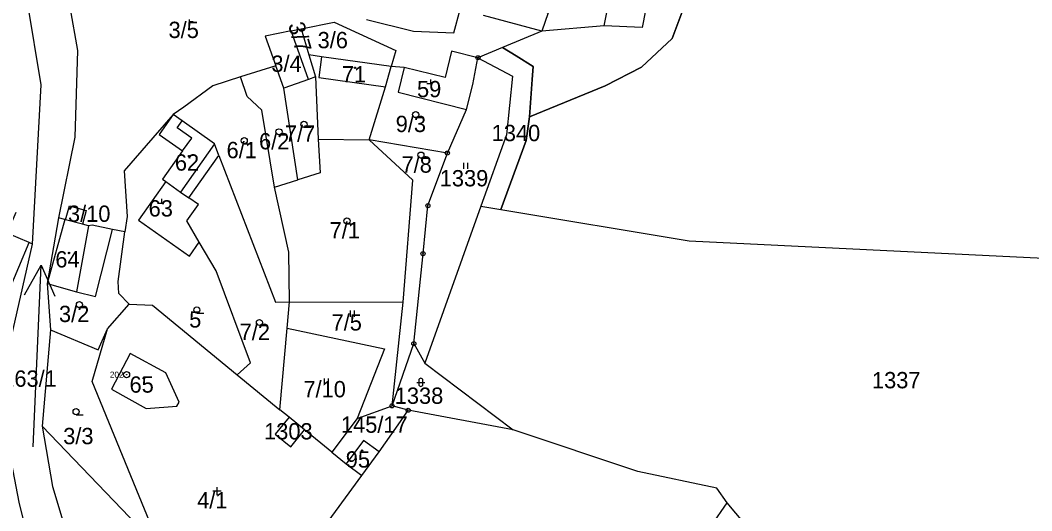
# Model space of a CAD drawing. Extents: x -564516 to -563466, y -1163913 to -1163170.
# Drawn here: x -564146.8 to -563898.7, y -1163610.3 to -1163490 of the extents above; entities that cross this region are included whole.
import ezdxf

# ---------------------------------------------------------------- set-up
doc = ezdxf.new("R2010")
doc.units = 0
for name, color, linetype in [('_ZOV', 7, 'Continuous'), ('Hranice parcel', 7, 'Continuous'), ('Parcelní čísla', 7, 'Continuous'), ('Vnitřní kresba', 7, 'Continuous'), ('Značky bodu BP', 7, 'Continuous'), ('Značky budov', 7, 'Continuous'), ('Značky kultur', 7, 'Continuous')]:
    doc.layers.add(name, color=color, linetype=linetype)

msp = doc.modelspace()

# ---------------------------------------------------------------- linework, layer by layer
at = {"layer": '_ZOV'}
msp.add_line((-564143.63, -1163594.64), (-564141.71, -1163550.07), dxfattribs=at)
msp.add_lwpolyline([(-564145.74, -1163557.34), (-564141.71, -1163550.07), (-564138.31, -1163557.66)], dxfattribs=at)
at = {"layer": 'Hranice parcel'}
for p, q in [((-564003.59, -1163491.36), (-564001.49, -1163481.27)), ((-564018.83, -1163492.67), (-564033.19, -1163488.88)), ((-564080.36, -1163492.63), (-564077.86, -1163492.12)), ((-564076.1, -1163504.52), (-564080.36, -1163492.63)), ((-564077.86, -1163492.12), (-564075.98, -1163498.54)), ((-564018.83, -1163492.67), (-564028.46, -1163496.69)), ((-564003.59, -1163491.36), (-564018.83, -1163492.67)), ((-564028.46, -1163496.69), (-564034.52, -1163499.22)), ((-564075.98, -1163498.54), (-564074.41, -1163503.9)), ((-564084.1, -1163501.17), (-564092.76, -1163503.91)), ((-564082.12, -1163506.7), (-564084.1, -1163501.17)), ((-564052.59, -1163501.62), (-564055.78, -1163501.39)), ((-564021.23, -1163504.52), (-564020.95, -1163501.38)), ((-564076.1, -1163504.52), (-564082.12, -1163506.7)), ((-564074.41, -1163503.9), (-564076.1, -1163504.52)), ((-564074.41, -1163503.9), (-564073.71, -1163519.16)), ((-564021.9, -1163513.74), (-564021.23, -1163504.52)), ((-564078.72, -1163529.15), (-564082.12, -1163506.7)), ((-564021.9, -1163513.74), (-564003.29, -1163506.07)), ((-564042.03, -1163522.61), (-564037.34, -1163511.95)), ((-564109.29, -1163513.17), (-564114.3, -1163518.86)), ((-564022.73, -1163519.5), (-564021.9, -1163513.74)), ((-564073.71, -1163519.16), (-564061.18, -1163519.39)), ((-564042.03, -1163522.61), (-564061.18, -1163519.39)), ((-564028.91, -1163536.42), (-564022.73, -1163519.5)), ((-564105.44, -1163533.59), (-564098.08, -1163523.21)), ((-564084.46, -1163530.94), (-564078.72, -1163529.15)), ((-564135.68, -1163538.95), (-564134.76, -1163535.58)), ((-564134.76, -1163535.58), (-564130.65, -1163536.7)), ((-564130.65, -1163536.7), (-564131.56, -1163540.01)), ((-564033.84, -1163535.6), (-564047.59, -1163574.1)), ((-564033.84, -1163535.6), (-564028.91, -1163536.42)), ((-564137.43, -1163538.5), (-564140.18, -1163554.63)), ((-564131.56, -1163540.01), (-564135.68, -1163538.95)), ((-564130.03, -1163540.41), (-564131.56, -1163540.01)), ((-564129.13, -1163540.27), (-564130.03, -1163540.41)), ((-564124.15, -1163541.32), (-564129.13, -1163540.27)), ((-564121.18, -1163541.94), (-564124.15, -1163541.32)), ((-564149.67, -1163556.63), (-564144.59, -1163544.5)), ((-564143.77, -1163544.97), (-564144.59, -1163544.5)), ((-564140.18, -1163554.63), (-564139.41, -1163565.96)), ((-564120.1, -1163559.69), (-564122.64, -1163557.02)), ((-564125.43, -1163565.71), (-564120.1, -1163559.69)), ((-564081.35, -1163565.54), (-564080.79, -1163559.09)), ((-564080.79, -1163559.09), (-564052.86, -1163559.2)), ((-564055.59, -1163584.6), (-564052.86, -1163559.2)), ((-564139.41, -1163565.96), (-564141.45, -1163589.58)), ((-564083.1, -1163585.56), (-564081.35, -1163565.54)), ((-564055.59, -1163584.6), (-564050.25, -1163569.33)), ((-564050.25, -1163569.33), (-564047.59, -1163574.1)), ((-564047.59, -1163574.1), (-564025.86, -1163590.51)), ((-564093.56, -1163576.99), (-564083.1, -1163585.56)), ((-564064.14, -1163587.67), (-564055.59, -1163584.6)), ((-564051.64, -1163585.68), (-564055.59, -1163584.6)), ((-564080.86, -1163587.4), (-564083.1, -1163585.56)), ((-564025.86, -1163590.51), (-564051.64, -1163585.68)), ((-564141.45, -1163589.58), (-564112.22, -1163619.96)), ((-564077.06, -1163590.51), (-564080.86, -1163587.4)), ((-564064.14, -1163587.67), (-564070.36, -1163596)), ((-564070.36, -1163596), (-564077.06, -1163590.51)), ((-564070.36, -1163596), (-564066.89, -1163598.84)), ((-564063.05, -1163601.67), (-564058.79, -1163595.9)), ((-564066.89, -1163598.84), (-564063.05, -1163601.67)), ((-564092.3, -1163641.63), (-564063.05, -1163601.67)), ((-563945.88, -1163641.11), (-563973.39, -1163608.38))]:
    msp.add_line(p, q, dxfattribs=at)
for points in [[(-564143.77, -1163544.97), (-564141.64, -1163505.89), (-564145.04, -1163485.62), (-564150.7, -1163460.95), (-564167.69, -1163413.52), (-564175.8, -1163398.73), (-564196.49, -1163371.97), (-564199.67, -1163364.72)], [(-563978.16, -1163460.35), (-563977.81, -1163470.18), (-563986.9, -1163494.46), (-563994.41, -1163501.54), (-564003.29, -1163506.07), (-564021.9, -1163513.74)], [(-563986.9, -1163494.46), (-563977.81, -1163470.18), (-563978.16, -1163460.35)], [(-563988.32, -1163461.72), (-563994.27, -1163491.83), (-564003.59, -1163491.36)], [(-564032.65, -1163483.65), (-564032.18, -1163483.66), (-564032.1, -1163484.76), (-564017.32, -1163488.18), (-564018.83, -1163492.67)], [(-564134.63, -1163486.82), (-564132.78, -1163497.42), (-564133.38, -1163518.72), (-564137.43, -1163538.5)], [(-564061.85, -1163489.87), (-564050.33, -1163492.71), (-564040.4, -1163493.1), (-564038.9, -1163487.37)], [(-564080.36, -1163492.63), (-564086.69, -1163493.92), (-564084.1, -1163501.17)], [(-564077.86, -1163492.12), (-564069.81, -1163490.48), (-564054.63, -1163497.47), (-564055.78, -1163501.39)], [(-564028.91, -1163536.42), (-563982.72, -1163544.1), (-563870.61, -1163549.59), (-563828.67, -1163493.21)], [(-564003.29, -1163506.07), (-563994.41, -1163501.54), (-563986.9, -1163494.46)], [(-564034.52, -1163499.22), (-564040.98, -1163497.58), (-564042.58, -1163504.09), (-564052.59, -1163501.62)], [(-564028.46, -1163496.69), (-564025.15, -1163498.74), (-564020.95, -1163501.38), (-564021.23, -1163504.52), (-564021.9, -1163513.74)], [(-564020.95, -1163501.38), (-564025.15, -1163498.74), (-564028.46, -1163496.69)], [(-564055.78, -1163501.39), (-564072.88, -1163498.98), (-564075.98, -1163498.54)], [(-564037.34, -1163511.95), (-564035.8, -1163505.76), (-564034.52, -1163499.22)], [(-564034.52, -1163499.22), (-564026.04, -1163503.72), (-564027.54, -1163518.14), (-564033.84, -1163535.6)], [(-564061.18, -1163519.39), (-564057.24, -1163506.38), (-564055.78, -1163501.39)], [(-564052.59, -1163501.62), (-564054.07, -1163507.64), (-564037.34, -1163511.95)], [(-564092.76, -1163503.91), (-564099.6, -1163506.08), (-564106.7, -1163511.31), (-564109.29, -1163513.17)], [(-564084.46, -1163530.94), (-564087.57, -1163512.11), (-564091.17, -1163508.73), (-564092.76, -1163503.91)], [(-564109.29, -1163513.17), (-564112.74, -1163518.03), (-564107.04, -1163522.06), (-564111.89, -1163529.04), (-564111.07, -1163529.61)], [(-564098.08, -1163523.21), (-564099.13, -1163520.36), (-564107.09, -1163514.73), (-564109.29, -1163513.17)], [(-564021.9, -1163513.74), (-564022.73, -1163519.5), (-564028.91, -1163536.42)], [(-564114.3, -1163518.86), (-564121.28, -1163526.92), (-564120.58, -1163538.19), (-564121.18, -1163541.94)], [(-564073.71, -1163519.16), (-564073.26, -1163527.42), (-564078.72, -1163529.15)], [(-564052.86, -1163559.2), (-564050.52, -1163529.28), (-564061.18, -1163519.39)], [(-564050.25, -1163569.33), (-564048, -1163547.27), (-564046.8, -1163535.5), (-564042.03, -1163522.61)], [(-564098.08, -1163523.21), (-564084.18, -1163559.19), (-564080.79, -1163559.09)], [(-564111.07, -1163529.61), (-564117.77, -1163539.08), (-564105.32, -1163547.88), (-564102.89, -1163544.44)], [(-564111.07, -1163529.61), (-564107.48, -1163532.15), (-564105.44, -1163533.59)], [(-564080.79, -1163559.09), (-564080.89, -1163546.94), (-564084.46, -1163530.94)], [(-564102.89, -1163544.44), (-564105.94, -1163539.23), (-564103.12, -1163535.23), (-564105.44, -1163533.59)], [(-564144.59, -1163544.5), (-564150.02, -1163542.22), (-564147.82, -1163537.06)], [(-564135.68, -1163538.95), (-564135.89, -1163538.9), (-564137.43, -1163538.5)], [(-564140.18, -1163554.63), (-564133.01, -1163556.6), (-564128.31, -1163557.75), (-564124.15, -1163541.32)], [(-564122.64, -1163557.02), (-564122.78, -1163554.08), (-564121.18, -1163541.94)], [(-564141.75, -1163629.73), (-564147.11, -1163608.19), (-564150.44, -1163590.7), (-564149.91, -1163571.99), (-564143.77, -1163544.97)], [(-564093.56, -1163576.99), (-564090.33, -1163574.05), (-564098.76, -1163551.48), (-564102.89, -1163544.44)], [(-564120.1, -1163559.69), (-564114.4, -1163559.92), (-564093.56, -1163576.99)], [(-564139.41, -1163565.96), (-564127.69, -1163570.84), (-564125.43, -1163565.71)], [(-564112.22, -1163619.96), (-564129.19, -1163578.66), (-564125.43, -1163565.71)], [(-564081.35, -1163565.54), (-564057.47, -1163570.58), (-564064.14, -1163587.67)], [(-564107.84, -1163583.68), (-564111.09, -1163576.51), (-564119.82, -1163571.78), (-564124.45, -1163580.53), (-564115.93, -1163585.25), (-564108.37, -1163584.67), (-564107.84, -1163583.68)], [(-564058.79, -1163595.9), (-564053.56, -1163588.43), (-564051.64, -1163585.68)], [(-564141.45, -1163589.58), (-564138.93, -1163604.36), (-564128.21, -1163640.02)], [(-564080.86, -1163587.4), (-564084.24, -1163591.54), (-564080.45, -1163594.65), (-564077.06, -1163590.51)], [(-563973.39, -1163608.38), (-563975.93, -1163604.8), (-563995.32, -1163600.73), (-564025.86, -1163590.51)], [(-564058.79, -1163595.9), (-564062.63, -1163593.07), (-564066.89, -1163598.84)], [(-564038.32, -1163697.37), (-564037.15, -1163696.07), (-563993.61, -1163632.54), (-563977.25, -1163613.92), (-563973.39, -1163608.38)]]:
    msp.add_lwpolyline(points, dxfattribs=at)
at = {"layer": 'Vnitřní kresba'}
for p, q in [((-564072.88, -1163498.98), (-564073.58, -1163504.08)), ((-564073.58, -1163504.08), (-564057.24, -1163506.38)), ((-564108.3, -1163516.44), (-564107.09, -1163514.73)), ((-564104.75, -1163518.95), (-564108.3, -1163516.44)), ((-564107.04, -1163522.06), (-564104.75, -1163518.95)), ((-564099.13, -1163520.36), (-564107.48, -1163532.15)), ((-564135.89, -1163538.9), (-564140.18, -1163554.63)), ((-564130.03, -1163540.41), (-564133.01, -1163556.6))]:
    msp.add_line(p, q, dxfattribs=at)
at = {"layer": 'Značky bodu BP'}
for centre, radius in [((-564034.52, -1163499.22), 0.5), ((-564034.52, -1163499.22), 0.0303), ((-564042.03, -1163522.61), 0.5), ((-564042.03, -1163522.61), 0.0303), ((-564046.8, -1163535.5), 0.5), ((-564046.8, -1163535.5), 0.0303), ((-564048, -1163547.27), 0.5), ((-564048, -1163547.27), 0.0303), ((-564050.25, -1163569.33), 0.5), ((-564050.25, -1163569.33), 0.0303), ((-564120.72, -1163576.96), 0.75), ((-564120.72, -1163576.96), 0.03), ((-564055.59, -1163584.6), 0.5), ((-564055.59, -1163584.6), 0.0303), ((-564051.64, -1163585.68), 0.5), ((-564051.64, -1163585.68), 0.0303)]:
    msp.add_circle(centre, radius, dxfattribs=at)
at = {"layer": 'Značky budov'}
for centre in [(-564064.7, -1163501.67), (-564105.39, -1163523.36), (-564134.82, -1163547.11), (-564116.56, -1163577.82), (-564062.93, -1163595.56)]:
    msp.add_circle(centre, 0.175, dxfattribs=at)
at = {"layer": 'Značky kultur'}
for p, q in [((-564105.41, -1163489.84), (-564105.41, -1163490.34)), ((-564105.41, -1163490.34), (-564104.41, -1163490.34)), ((-564046.05, -1163505.57), (-564046.05, -1163504.57)), ((-564047.05, -1163505.57), (-564046.05, -1163505.57)), ((-564049.79, -1163513.9), (-564048.04, -1163513.9)), ((-564077.2, -1163516.28), (-564075.45, -1163516.28)), ((-564083.34, -1163518.14), (-564081.59, -1163518.14)), ((-564091.87, -1163520.31), (-564090.12, -1163520.31)), ((-564048.51, -1163523.86), (-564046.76, -1163523.86)), ((-564038.01, -1163526.5), (-564038.01, -1163525)), ((-564037.01, -1163526.5), (-564037.01, -1163525)), ((-564113.1, -1163534.86), (-564112.1, -1163534.86)), ((-564112.1, -1163534.86), (-564112.1, -1163533.86)), ((-564066.65, -1163539.99), (-564064.9, -1163539.99)), ((-564132.3, -1163560.5), (-564130.55, -1163560.5)), ((-564103.49, -1163561.85), (-564101.74, -1163561.85)), ((-564065.8, -1163562.75), (-564065.8, -1163561.25)), ((-564064.8, -1163562.75), (-564064.8, -1163561.25)), ((-564088.14, -1163564.91), (-564086.39, -1163564.91)), ((-564072.15, -1163579.42), (-564072.15, -1163577.92)), ((-564071.15, -1163579.42), (-564071.15, -1163577.92)), ((-564049.54, -1163578.84), (-564047.54, -1163578.84)), ((-564049.04, -1163578.34), (-564049.04, -1163579.34)), ((-564048.04, -1163579.34), (-564048.04, -1163578.34)), ((-564133.11, -1163586.77), (-564131.36, -1163586.77)), ((-564098.53, -1163606.52), (-564098.53, -1163604.52)), ((-564097.53, -1163605.52), (-564099.53, -1163605.52))]:
    msp.add_line(p, q, dxfattribs=at)
for centre in [(-564049.79, -1163513.15), (-564077.2, -1163515.53), (-564083.34, -1163517.39), (-564091.87, -1163519.56), (-564048.51, -1163523.11), (-564066.65, -1163539.24), (-564132.3, -1163559.75), (-564103.49, -1163561.1), (-564088.14, -1163564.16), (-564133.11, -1163586.02)]:
    msp.add_circle(centre, 0.75, dxfattribs=at)
for centre, start, end in [((-564048.54, -1163578.34), 0, 180), ((-564048.54, -1163579.34), 180, 359.9879)]:
    msp.add_arc(centre, 0.5, start, end, dxfattribs=at)

# ---------------------------------------------------------------- texts
at = {"layer": 'Parcelní čísla'}
for s, p in [('3/5', (-564110.43, -1163494.38)), ('3/6', (-564073.86, -1163496.89)), ('3/4', (-564085.2, -1163502.68)), ('71', (-564067.91, -1163505.28)), ('59', (-564049.47, -1163508.91)), ('9/3', (-564054.7, -1163517.45)), ('6/2', (-564088.23, -1163521.69)), ('7/7', (-564081.88, -1163519.83)), ('1340', (-564031.15, -1163519.68)), ('6/1', (-564096.19, -1163523.86)), ('62', (-564108.87, -1163526.91)), ('7/8', (-564053.27, -1163527.41)), ('1339', (-564043.89, -1163530.77)), ('63', (-564115.31, -1163538.16)), ('3/10', (-564135.1, -1163539.47)), ('7/1', (-564070.91, -1163543.54)), ('64', (-564138.2, -1163550.66)), ('3/2', (-564137.31, -1163564.05)), ('5', (-564105.37, -1163565.4)), ('7/5', (-564070.43, -1163566.13)), ('7/2', (-564092.98, -1163568.46)), ('1163/1', (-564154.2, -1163579.92)), ('1337', (-563937.85, -1163580.3)), ('65', (-564120, -1163581.37)), ('7/10', (-564077.34, -1163582.51)), ('1338', (-564054.93, -1163584.11)), ('145/17', (-564068.13, -1163591.21)), ('1303', (-564086.99, -1163592.84)), ('3/3', (-564136.27, -1163594.01)), ('95', (-564066.95, -1163599.75)), ('4/1', (-564103.41, -1163609.77))]:
    msp.add_text(s, height=4, dxfattribs=at).set_placement(p)
msp.add_text('3/7', height=4, rotation=286, dxfattribs=at).set_placement((-564081.14, -1163491.1))
at = {"layer": 'Značky bodu BP'}
msp.add_text('202', height=1.5, dxfattribs=at).set_placement((-564124.82, -1163577.71))

doc.saveas('drawing.dxf')
